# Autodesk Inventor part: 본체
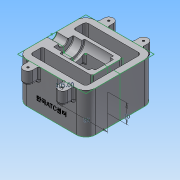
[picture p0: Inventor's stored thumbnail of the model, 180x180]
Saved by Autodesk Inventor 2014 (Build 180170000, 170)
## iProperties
Created: 2018-01
Part Number: 본체
Material: 알루미늄 6061
Document SubType Name: Modeling
Designer: 601-25
Density: 2.71 g/cm^3
Appearance: 알루미늄 - 평지
Mass: 995.137 g
Surface Area: 835.914 cm^2
Volume: 367.209 cm^3
Author: 601-25
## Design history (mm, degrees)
sketch "스케치1"
  geometry: L1 (55, -55)-(-55, -55); L2 (-55, -55)-(-55, 55); L3 (-55, 55)-(55, 55); L4 (55, 55)-(55, -55); L5 (55, -55)-(-55, 55); L6 (-55, -55)-(55, 55); 1 further point
  constraints: 12 end point, 2 midpoint, 2 parallel, 1 horizontal, 1 perpendicular
  dimensions: "d0" = 110 distance of L2.end L3.end; "d1" = 110 distance of L1.end L2.end
extrude "돌출1" new body sketch "스케치1" stored distance "d2" = 65; taper "d3" = 0 deg
sketch "스케치2"
  geometry: L1 (-55, -55)-(55, -55) reference; L2 (55, -55)-(55, 55) reference; L3 (55, 55)-(-55, 55) reference; L4 (-55, 55)-(-55, -55) reference; 1 further point
fillet "모깎기1" dims "d4" = 15
sketch "스케치3" dims "d10" = 0
  geometry: L1 (-55, 40)-(-55, -40) reference; L2 (45, 25)-(-45, 25); L3 (-45, 25)-(-45, 45); L4 (-45, 45)-(45, 45); L5 (45, 45)-(45, 25); L6 (45, 25)-(-45, 45); L7 (-45, 25)-(45, 45); L8 (-40, 55)-(40, 55) reference; 7 further points
  constraints: 12 end point, 8 point on line, 5 horizontal, 4 vertical, 3 midpoint, 2 parallel, 1 perpendicular, 1 vertical alignment, 16 other
  dimensions: "d7" = 10 distance between parallel lines of L4 L8; "d8" = 10 distance between parallel lines of L3 L1; "d9" = 20 distance of L7.start L6.end
extrude "돌출2" cut sketch "스케치3" stored distance "d11" = 65; taper "d12" = 0 deg
sketch "스케치4"
  geometry: L1 (55, -40)-(55, 40) reference; L2 (42, -45)-(35, -45); L3 (35, -45)-(35, 45); L4 (35, 45)-(40, 45); L5 (45, 40)-(45, -42); L6 (45, -45)-(35, 45); L7 (35, -45)-(45, 45); A1 r 5 centre (40, 40) between (45, 40) and (40, 45); A2 r 3 centre (42, -42) between (42, -45) and (45, -42); 3 further points
  constraints: 12 end point, 4 point on circle, 4 point on line, 4 tangent, 3 midpoint, 2 centre point, 2 parallel, 1 horizontal, 1 horizontal alignment, 1 perpendicular
  dimensions: "d16" = 10 distance between parallel lines of L1 L5; "d17" = 20 distance between parallel lines of L1 L3; "d18" = 90 distance of L7.end L6.start; "d19" = 5 radius of A1; "d20" = 3 radius of A2
extrude "돌출3" cut sketch "스케치4" stored distance "d21" = 65; taper "d22" = 0 deg
sketch "스케치6"
  geometry: L1 (0, 80)-(0, 0) reference; C1 r 7.5 at (0, 40); 1 further point
  constraints: 1 centre point, 1 midpoint
  dimensions: "d24" = 15 diameter of C1
extrude "돌출4" cut sketch "스케치6" distance "d25" = 19; taper "d26" = 0 deg
sketch "스케치7"
  geometry: C1 r 16 at (0, 40); A1 r 7.5 centre (0, 40) between (0, 47.5) and (0, 32.5) reference; 1 further point
  constraints: 1 centre point, 1 coincident
  dimensions: "d27" = 32 diameter of C1
extrude "돌출5" cut sketch "스케치7" distance "d28" = 14; taper "d29" = 0 deg
sketch "스케치8"
  geometry: C1 r 20 at (0, 40); A1 r 16 centre (0, 40) between (0, 56) and (0, 24) reference; 1 further point
  constraints: 1 centre point, 1 coincident
  dimensions: "d30" = 40 diameter of C1
extrude "돌출6" cut sketch "스케치8" distance "d31" = 47; taper "d32" = 0 deg
sketch "스케치9"
  geometry: C1 r 15 at (0, 40); A1 r 20 centre (0, 40) between (0, 60) and (0, 20) reference; 1 further point
  constraints: 1 centre point, 1 coincident
  dimensions: "d33" = 30 diameter of C1
extrude "돌출7" cut sketch "스케치9" distance "d34" = 5; taper "d35" = 0 deg
sketch "스케치10"
  geometry: L1 (65, 80)-(65, 47.5) reference; L2 (0, 80)-(65, 80) reference; L3 (0, 0)-(0, 80) reference; L4 (65, 0)-(0, 0) reference; L5 (65, 32.5)-(65, 0) reference; A1 r 7.5 centre (65, 40) between (65, 47.5) and (65, 32.5) reference; 1 further point
sketch "스케치11"
  geometry: L1 (-22, 16)-(-22, 20) reference; L2 (20, -15)-(-17, -15); L3 (-17, -15)-(-17, 15); L4 (-17, 15)-(20, 15); L5 (20, 15)-(20, -15); L6 (20, -15)-(-17, 15); L7 (-17, -15)-(20, 15); 3 further points
  constraints: 12 end point, 3 midpoint, 2 parallel, 1 horizontal, 1 horizontal alignment, 1 perpendicular
  dimensions: "d36" = 37 distance of L3.end L4.end; "d37" = 30 distance of L2.end L3.end; "d38" = 5 distance between parallel lines of L3 L1
sketch "스케치12"
  geometry: L1 (40, 55)-(-40, 55) reference; L2 (-55, 40)-(-55, 7.5) reference; L3 (-35.5, 65)-(-35.5, 55); L4 (-20.5, 65)-(-20.5, 55); L5 (-35.5, 55)-(-20.5, 55); A1 r 7.5 centre (-28, 65) between (-20.5, 65) and (-35.5, 65); 1 further point
  constraints: 6 end point, 2 perpendicular, 2 point on circle, 2 point on line, 2 tangent, 1 centre point, 1 collinear
  dimensions: "d39" = 7.5 radius of A1; "d40" = 27 distance from line of A1.centre L2; "d41" = 10 distance from line of L1 A1.centre
extrude "돌출8" join sketch "스케치12" distance "d42" = 20; taper "d43" = 0 deg
sketch "스케치13"
  geometry: L1 (65, 80)-(65, 47.5) reference; L2 (0, 80)-(65, 80) reference; L3 (0, 0)-(0, 80) reference; L4 (65, 0)-(0, 0) reference; L5 (65, 32.5)-(65, 0) reference; A1 r 7.5 centre (65, 40) between (65, 47.5) and (65, 32.5) reference; 1 further point
sketch "스케치14"
  geometry: L1 (45, -45)-(-45, -45) reference; L2 (-45, -45)-(-45, 45) reference; L3 (-45, 45)-(45, 45) reference; L4 (45, 45)-(45, 25) reference; L5 (45, 25)-(-35, 25) reference; L6 (-35, 25)-(-35, -25) reference; L7 (-35, -25)-(45, -25) reference; L8 (45, -25)-(45, -45) reference; L9 (-55, 40)-(-55, -40) reference; L10 (-40, -55)-(40, -55) reference; L11 (55, -40)-(55, 40) reference; L12 (40, 55)-(-40, 55) reference; A1 r 15 centre (-40, 40) between (-40, 55) and (-55, 40) reference; A2 r 15 centre (-40, -40) between (-55, -40) and (-40, -55) reference; A3 r 15 centre (40, -40) between (40, -55) and (55, -40) reference; A4 r 15 centre (40, 40) between (55, 40) and (40, 55) reference; 1 further point
extrude "돌출9" cut sketch "스케치11" distance "d44" = 35; taper "d45" = 0 deg
sketch "스케치22"
  geometry: L1 (-20, -2.5)-(55, -22.596); L2 (-55, 32.5)-(-45, 32.5) reference; L3 (-45, 32.5)-(-45, -32.5) reference; L4 (-45, -32.5)-(-55, -32.5) reference; L5 (-55, -32.5)-(-55, 32.5) reference; L6 (36, 16.5)-(36, 25) reference; L7 (36, 25)-(55, 25) reference; L8 (55, 25)-(55, -32.5) reference; L9 (55, -32.5)-(-35, -32.5) reference; L10 (-35, -32.5)-(-35, 32.5) reference; L11 (-35, 32.5)-(-30, 32.5) reference; L12 (-30, 32.5)-(-30, 17.5) reference; L13 (-30, 17.5)-(-25, 17.5) reference; L14 (-25, 17.5)-(-25, 12.5) reference; L15 (-25, 12.5)-(-20, 12.5) reference; L16 (-20, 12.5)-(-20, -2.5) reference; L17 (-20, -2.5)-(17, -2.5) reference; L18 (17, -2.5)-(17, 12.5) reference; L19 (17, 12.5)-(22, 12.5) reference; L20 (22, 12.5)-(22, 16.5) reference; L21 (22, 16.5)-(36, 16.5) reference; L22 (55, -4.596)-(17, 5.586); L23 (55, -4.596)-(55, -22.596); L24 (17, 5.586)-(17, -2.5); L25 (17, -2.5)-(-20, -2.5); L26 (-20, -2.5)-(17, -2.5) reference; 1 further point
  constraints: 10 end point, 3 collinear, 3 point on line, 1 parallel
  dimensions: "d73" = 75 deg angle of L8 L1; "d74" = 18 distance of L1.end L22.start
  node "절단 모서리 투영4"
extrude "돌출12" cut sketch "스케치22" distance "d75" = 15; taper "d76" = 0 deg
extrude "돌출13" cut sketch "스케치22" distance "d77" = 15; taper "d78" = 0 deg
sketch "스케치27"
  geometry: A1 r 7.5 centre (-28, 65) between (-20.5, 65) and (-35.5, 65) reference; 2 further points
  constraints: 1 coincident
hole "구멍1" sketch "스케치27" at (-28, 65) diameter "d89" = 3.242; stored, may be unused: countersink angle "d93" = 90 deg, drill point angle "d95" = 118 deg; dims "d90" = 9, "d91" = 4, "d92" = 2, "d94" = 11
sketch "스케치28"
  geometry: L1 (80, 0)-(0, 0) reference; L2 (-15, 65)-(-15, 0) reference; 2 further points
  constraints: 1 other
  dimensions: "d96" = 20 distance from line of L1 point (40, 20); "d97" = 55 distance from line of L2 point (40, 20)
feature "엠보싱1" sketch "스케치28" dims "d98" = 0.5, "d99" = 0
sketch "스케치29"
  geometry: L1 (0, -50)-(65, -50) reference; L2 (65, 0)-(65, -50) reference; L3 (0, 0)-(65, 0) reference; L4 (0, -50)-(0, 0) reference; 1 further point
fillet "모깎기2" dims "d100" = 5
fillet "모깎기3" dims "d101" = 3
fillet "모깎기4" dims "d102" = 3
fillet "모깎기5" dims "d103" = 3
fillet "모깎기6" dims "d107" = 1
chamfer "모따기2" distance "d108" = 1; stored, may be unused: second distance "d109" = 2, angle "d110" = 45 deg
fillet "모깎기7" dims "d117" = 3
sketch "스케치32"
  geometry: L1 (-55, 32.5)-(-45, 32.5) reference; L2 (-45, 32.5)-(-45, -32.5) reference; L3 (-45, -32.5)-(-55, -32.5) reference; L4 (-55, -32.5)-(-55, 32.5) reference; L5 (22, 13.5)-(22, 16.5) reference; L6 (22, 16.5)-(35, 16.5) reference; L7 (36, 17.5)-(36, 24) reference; L8 (36, 24)-(37, 25) reference; L9 (37, 25)-(54, 25) reference; L10 (54, 25)-(55, 24) reference; L11 (55, 24)-(55, -4.596) reference; L12 (55, -4.596)-(17, 5.586) reference; L13 (17, 5.586)-(17, 12.5) reference; L14 (17, 12.5)-(21, 12.5) reference; L15 (-29, 17.5)-(-25, 17.5) reference; L16 (-25, 17.5)-(-25, 13.5) reference; L17 (-24, 12.5)-(-20, 12.5) reference; L18 (-20, 12.5)-(-20, -2.5) reference; L19 (-20, -2.5)-(55, -22.596) reference; L20 (55, -22.596)-(55, -32.5) reference; L21 (55, -32.5)-(-35, -32.5) reference; L22 (-35, -32.5)-(-35, 32.5) reference; L23 (-35, 32.5)-(-30, 32.5) reference; L24 (-30, 32.5)-(-30, 18.5) reference; L25 (-40, 32.5)-(-40, -32.5) reference; L26 (-35, -2.5)-(45, -23.936); L27 (45, -23.936)-(45, -32.5); A1 r 1 centre (21, 13.5) between (21, 12.5) and (22, 13.5) reference; A2 r 1 centre (35, 17.5) between (35, 16.5) and (36, 17.5) reference; A3 r 1 centre (-29, 18.5) between (-30, 18.5) and (-29, 17.5) reference; A4 r 1 centre (-24, 13.5) between (-25, 13.5) and (-24, 12.5) reference; 1 further point
  constraints: 4 end point, 2 point on line, 1 perpendicular
  dimensions: "d119" = 30 distance of L21.end L26.start; "d120" = 105 deg angle of L27 L26; "d126" = 80 horizontal distance of L26.end L26.start
  node "절단 모서리 투영8"
sketch "스케치34"
  geometry: 1 further point
extrude "돌출16" cut sketch "스케치32" stored distance "d124" = 50; taper "d125" = 0 deg
fillet "모깎기10" dims "d129" = 3
fillet "모깎기11" dims "d130" = 3
fillet "모깎기12" dims "d131" = 5
fillet "모깎기13" dims "d132" = 3
node "솔리드1"
mirror "대칭1"
mirror "대칭2"
mirror "대칭3"
mirror "대칭4"
mirror "대칭5"
